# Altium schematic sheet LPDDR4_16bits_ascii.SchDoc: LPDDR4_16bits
size A3; Date: Not used; ApprovedBy: Not used; CheckedBy: Not used; Author: Not used; CompanyName: STMicroelectronics; DrawnBy: Not used; Engineer: Not used; Organization: Not used; Address1: Not used; Address2: Not used; Address3: Not used; Address4: Not used; DocumentNumber: 6; Revision: Not used; SheetNumber: 6; SheetTotal: 7
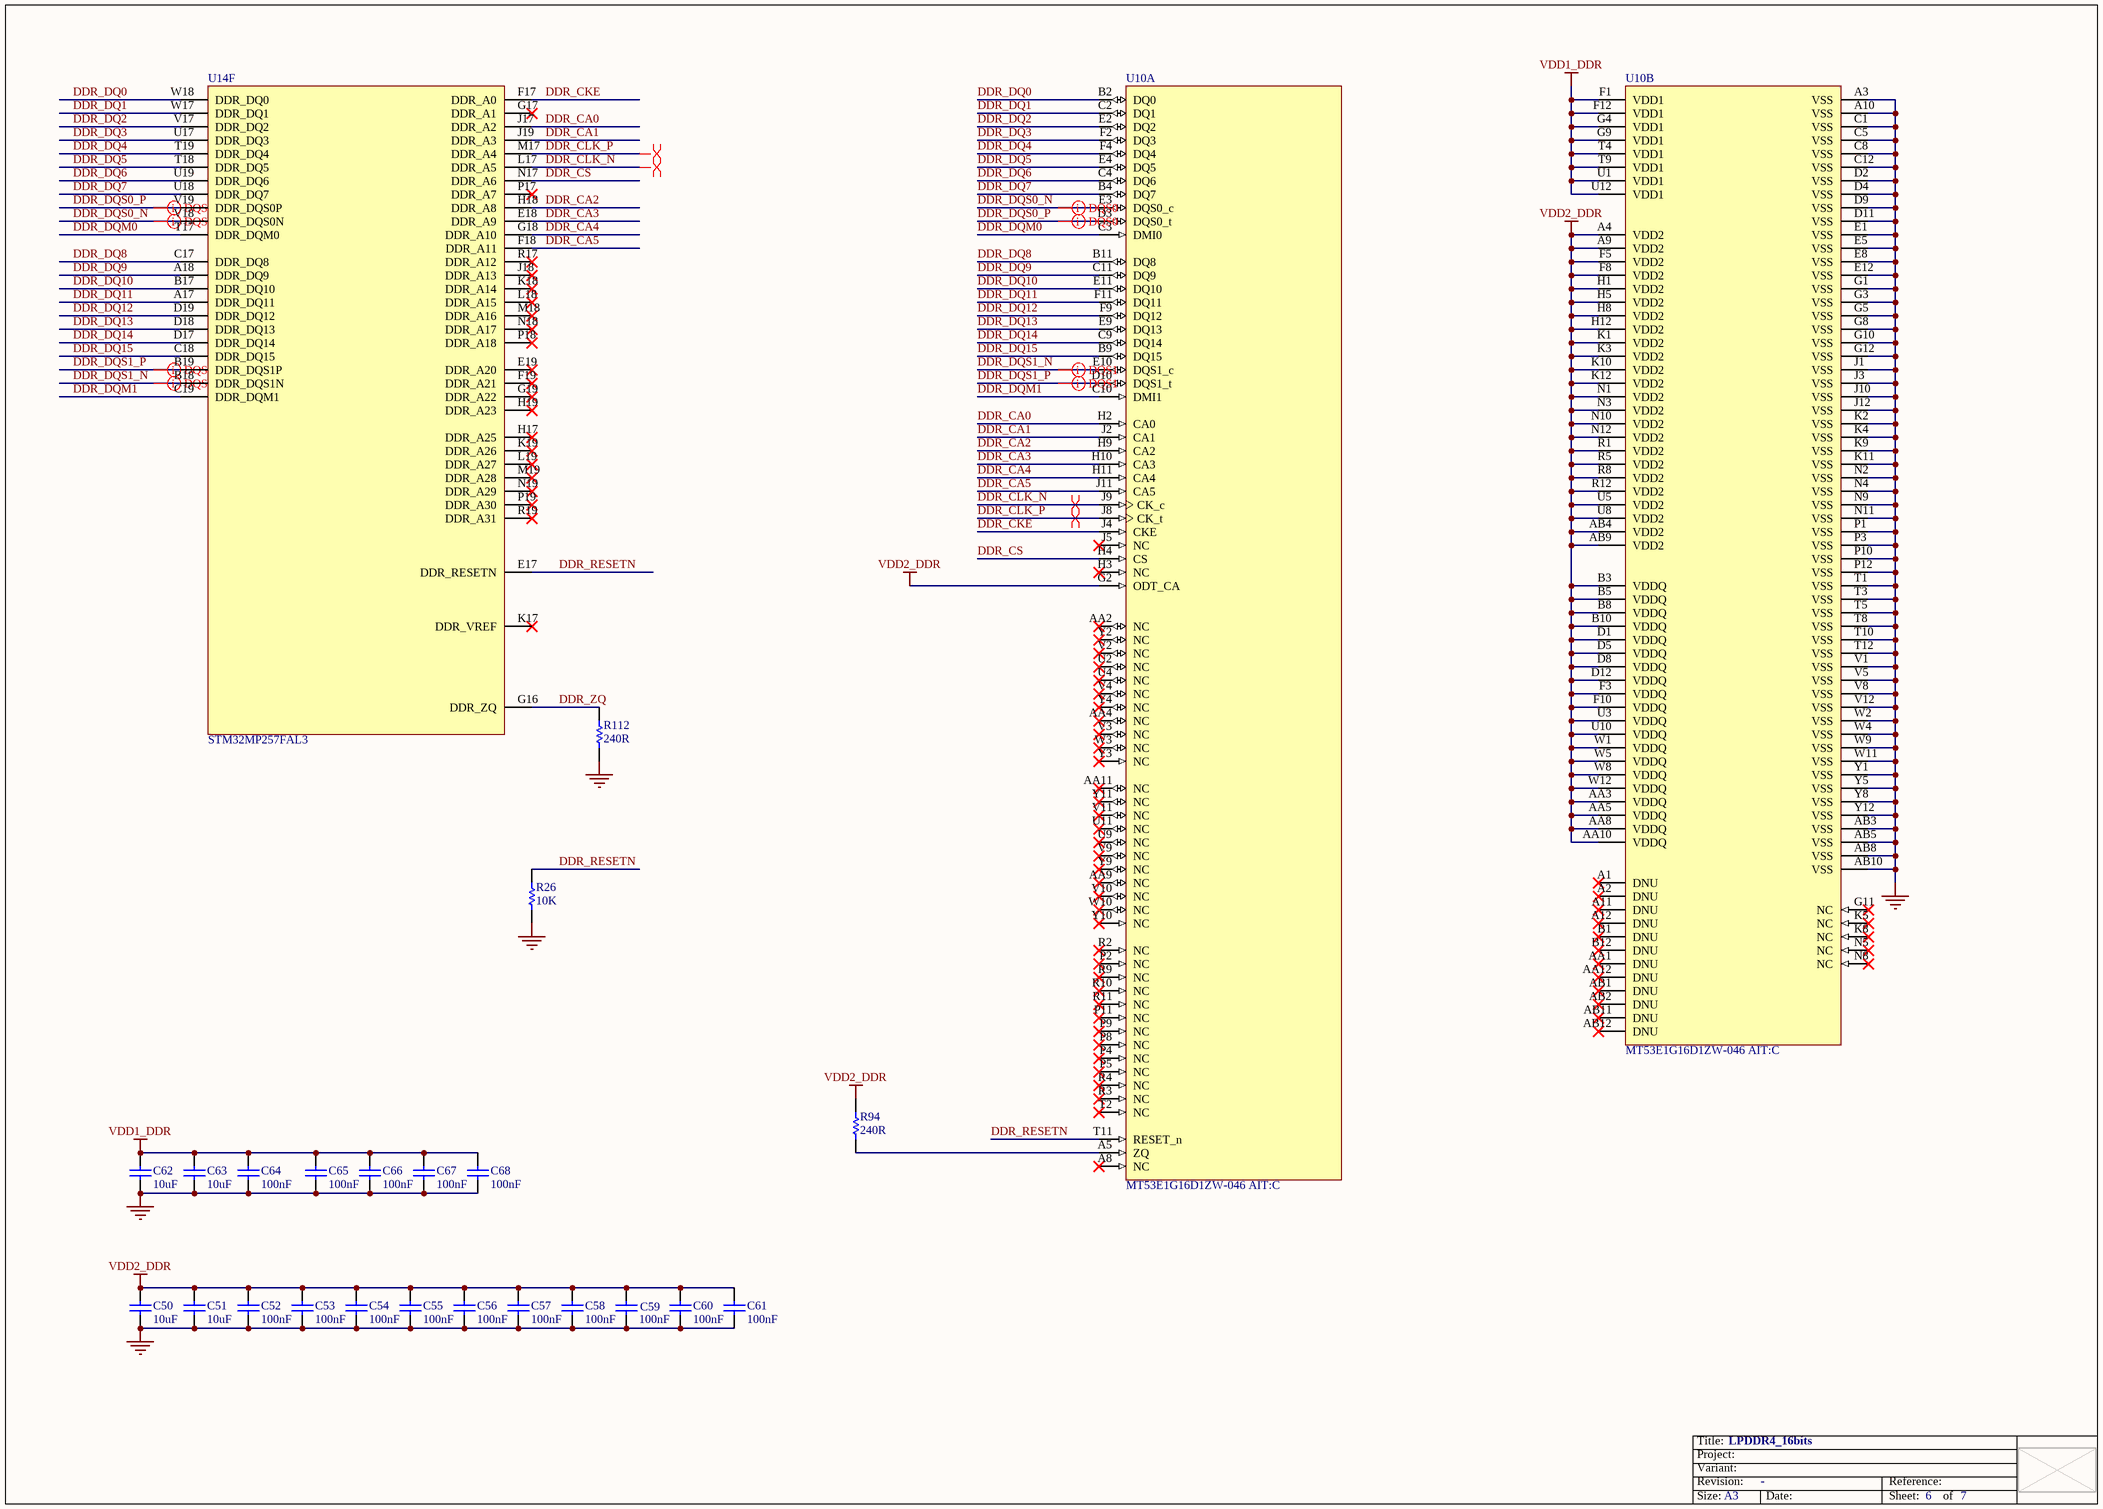
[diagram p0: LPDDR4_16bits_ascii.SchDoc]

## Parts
C50  value 10uF  [C0603]  (hidden comment: Capacitor)
C51  value 10uF  [C0603]  (hidden comment: Capacitor)
C52  value 100nF  [C0402]  (hidden comment: Capacitor)
C53  value 100nF  [C0402]  (hidden comment: Capacitor)
C54  value 100nF  [C0402]  (hidden comment: Capacitor)
C55  value 100nF  [C0402]  (hidden comment: Capacitor)
C56  value 100nF  [C0402]  (hidden comment: Capacitor)
C57  value 100nF  [C0402]  (hidden comment: Capacitor)
C58  value 100nF  [C0402]  (hidden comment: Capacitor)
C59  value 100nF  [C0402]  (hidden comment: Capacitor)
C60  value 100nF  [C0402]  (hidden comment: Capacitor)
C61  value 100nF  [C0402]  (hidden comment: Capacitor)
C62  value 10uF  [C0603]  (hidden comment: Capacitor)
C63  value 10uF  [C0603]  (hidden comment: Capacitor)
C64  value 100nF  [C0402]  (hidden comment: Capacitor)
C65  value 100nF  [C0402]  (hidden comment: Capacitor)
C66  value 100nF  [C0402]  (hidden comment: Capacitor)
C67  value 100nF  [C0402]  (hidden comment: Capacitor)
C68  value 100nF  [C0402]  (hidden comment: Capacitor)
R26  value 10K  [R0402]  (hidden comment: Resistor)
R94  value 240R  [R0201_H0P23]  (hidden comment: Resistor)
R112  value 240R  [R0201_H0P23]  (hidden comment: Resistor)
U10  MT53E1G16D1ZW-046 AIT:C  [ICC_TFBGA200_10X14P5_P080_H1P05]  (parts A,B of 2)
U14  STM32MP257FAL3  [ICC_VFBGA361_10X10_P050]  (part F of 8)

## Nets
GND: C50.1 C51.1 C52.1 C53.2 C54.2 C55.2 C56.2 C57.2 C58.2 C59.2 C60.2 C61.2 C62.1 C63.1 C64.1 C65.1 C66.1 C67.1 C68.1 R26.1 R112.1 U10.A3(VSS) U10.A10(VSS) U10.AB3(VSS) U10.AB5(VSS) U10.AB8(VSS) U10.AB10(VSS) U10.C1(VSS) U10.C5(VSS) U10.C8(VSS) U10.C12(VSS) U10.D2(VSS) U10.D4(VSS) U10.D9(VSS) U10.D11(VSS) U10.E1(VSS) U10.E5(VSS) U10.E8(VSS) U10.E12(VSS) U10.G1(VSS) U10.G3(VSS) U10.G5(VSS) U10.G8(VSS) U10.G10(VSS) U10.G12(VSS) U10.J1(VSS) U10.J3(VSS) U10.J10(VSS) U10.J12(VSS) U10.K2(VSS) U10.K4(VSS) U10.K9(VSS) U10.K11(VSS) U10.N2(VSS) U10.N4(VSS) U10.N9(VSS) U10.N11(VSS) U10.P1(VSS) U10.P3(VSS) U10.P10(VSS) U10.P12(VSS) U10.T1(VSS) U10.T3(VSS) U10.T5(VSS) U10.T8(VSS) U10.T10(VSS) U10.T12(VSS) U10.V1(VSS) U10.V5(VSS) U10.V8(VSS) U10.V12(VSS) U10.W2(VSS) U10.W4(VSS) U10.W9(VSS) U10.W11(VSS) U10.Y1(VSS) U10.Y5(VSS) U10.Y8(VSS) U10.Y12(VSS)
VDD1_DDR: C62.2 C63.2 C64.2 C65.2 C66.2 C67.2 C68.2 U10.F1(VDD1) U10.F12(VDD1) U10.G4(VDD1) U10.G9(VDD1) U10.T4(VDD1) U10.T9(VDD1) U10.U1(VDD1) U10.U12(VDD1)
VDD2_DDR: C50.2 C51.2 C52.2 C53.1 C54.1 C55.1 C56.1 C57.1 C58.1 C59.1 C60.1 C61.1 R94.2 U10.A4(VDD2) U10.A9(VDD2) U10.AA3(VDDQ) U10.AA5(VDDQ) U10.AA8(VDDQ) U10.AA10(VDDQ) U10.AB4(VDD2) U10.AB9(VDD2) U10.B3(VDDQ) U10.B5(VDDQ) U10.B8(VDDQ) U10.B10(VDDQ) U10.D1(VDDQ) U10.D5(VDDQ) U10.D8(VDDQ) U10.D12(VDDQ) U10.F3(VDDQ) U10.F5(VDD2) U10.F8(VDD2) U10.F10(VDDQ) U10.G2(ODT_CA) U10.H1(VDD2) U10.H5(VDD2) U10.H8(VDD2) U10.H12(VDD2) U10.K1(VDD2) U10.K3(VDD2) U10.K10(VDD2) U10.K12(VDD2) U10.N1(VDD2) U10.N3(VDD2) U10.N10(VDD2) U10.N12(VDD2) U10.R1(VDD2) U10.R5(VDD2) U10.R8(VDD2) U10.R12(VDD2) U10.U3(VDDQ) U10.U5(VDD2) U10.U8(VDD2) U10.U10(VDDQ) U10.W1(VDDQ) U10.W5(VDDQ) U10.W8(VDDQ) U10.W12(VDDQ)
DDR_CA0: U10.H2(CA0) U14.J17(DDR_A2)
DDR_CA1: U10.J2(CA1) U14.J19(DDR_A3)
DDR_CA2: U10.H9(CA2) U14.H18(DDR_A8)
DDR_CA3: U10.H10(CA3) U14.E18(DDR_A9)
DDR_CA4: U10.H11(CA4) U14.G18(DDR_A10)
DDR_CA5: U10.J11(CA5) U14.F18(DDR_A11)
DDR_CKE: U10.J4(CKE) U14.F17(DDR_A0)
DDR_CLK_N: U10.J9(CK_c) U14.L17(DDR_A5)
DDR_CLK_P: U10.J8(CK_t) U14.M17(DDR_A4)
DDR_CS: U10.H4(CS) U14.N17(DDR_A6)
DDR_DQ0: U10.B2(DQ0) U14.W18(DDR_DQ0)
DDR_DQ1: U10.C2(DQ1) U14.W17(DDR_DQ1)
DDR_DQ2: U10.E2(DQ2) U14.V17(DDR_DQ2)
DDR_DQ3: U10.F2(DQ3) U14.U17(DDR_DQ3)
DDR_DQ4: U10.F4(DQ4) U14.T19(DDR_DQ4)
DDR_DQ5: U10.E4(DQ5) U14.T18(DDR_DQ5)
DDR_DQ6: U10.C4(DQ6) U14.U19(DDR_DQ6)
DDR_DQ7: U10.B4(DQ7) U14.U18(DDR_DQ7)
DDR_DQ8: U10.B11(DQ8) U14.C17(DDR_DQ8)
DDR_DQ9: U10.C11(DQ9) U14.A18(DDR_DQ9)
DDR_DQ10: U10.E11(DQ10) U14.B17(DDR_DQ10)
DDR_DQ11: U10.F11(DQ11) U14.A17(DDR_DQ11)
DDR_DQ12: U10.F9(DQ12) U14.D19(DDR_DQ12)
DDR_DQ13: U10.E9(DQ13) U14.D18(DDR_DQ13)
DDR_DQ14: U10.C9(DQ14) U14.D17(DDR_DQ14)
DDR_DQ15: U10.B9(DQ15) U14.C18(DDR_DQ15)
DDR_DQM0: U10.C3(DMI0) U14.T17(DDR_DQM0)
DDR_DQM1: U10.C10(DMI1) U14.C19(DDR_DQM1)
DDR_DQS0_N: U10.E3(DQS0_c) U14.V18(DDR_DQS0N)
DDR_DQS0_P: U10.D3(DQS0_t) U14.V19(DDR_DQS0P)
DDR_DQS1_N: U10.E10(DQS1_c) U14.B18(DDR_DQS1N)
DDR_DQS1_P: U10.D10(DQS1_t) U14.B19(DDR_DQS1P)
DDR_RESETN: R26.2 U10.T11(RESET_n) U14.E17(DDR_RESETN)
DDR_ZQ: R112.2 U14.G16(DDR_ZQ)
NetR94_1: R94.1 U10.A5(ZQ)

Not connected (* = marked no-connect by the designer): U10 A1(DNU)* A2(DNU)* A8(NC)* A11(DNU)* A12(DNU)* AA1(DNU)* AA2(NC)* AA4(NC)* AA9(NC)* AA11(NC)* AA12(DNU)* AB1(DNU)* AB2(DNU)* AB11(DNU)* AB12(DNU)* B1(DNU)* B12(DNU)* G11(NC)* H3(NC)* J5(NC)* K5(NC)* K8(NC)* N5(NC)* N8(NC)* P2(NC)* P4(NC)* P5(NC)* P8(NC)* P9(NC)* P11(NC)* R2(NC)* R3(NC)* R4(NC)* R9(NC)* R10(NC)* R11(NC)* T2(NC)* U2(NC)* U4(NC)* U9(NC)* U11(NC)* V2(NC)* V3(NC)* V4(NC)* V9(NC)* V10(NC)* V11(NC)* W3(NC)* W10(NC)* Y2(NC)* Y3(NC)* Y4(NC)* Y9(NC)* Y10(NC)* Y11(NC)*; U14 E19(DDR_A20)* F19(DDR_A21)* G17(DDR_A1)* G19(DDR_A22)* H17(DDR_A25)* H19(DDR_A23)* J18(DDR_A13)* K17(DDR_VREF)* K18(DDR_A14)* K19(DDR_A26)* L18(DDR_A15)* L19(DDR_A27)* M18(DDR_A16)* M19(DDR_A28)* N18(DDR_A17)* N19(DDR_A29)* P17(DDR_A7)* P18(DDR_A18)* P19(DDR_A30)* R17(DDR_A12)* R19(DDR_A31)*

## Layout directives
differential pair: DDR_CLK_N, DDR_CLK_P, DDR_DQS0_N, DDR_DQS0_P, DDR_DQS1_N, DDR_DQS1_P

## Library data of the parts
C50 C51 C62 C63 = MCD-01341: Capacitor, MLCC, 10uF, 6V3, X5R, +/-20%, 0603, T=0.8mm; Part_Preference: Recommended; Manufacturer: MURATA; Manufacturer_Part_Number: GRM188R60J106ME47D; Component_Country_Of_Origin: Japan°°; ShowFields: YES; ID: 3441
C52-C61 C64-C68 = MCD-00006: Capacitor, MLCC, 100nF, 16V, X7R, +/-10%, 0402, T=0.5mm; Part_Preference: Recommended; Manufacturer: YAGEO; Manufacturer_Part_Number: CC0402KRX7R7BB104; Partial_Alternate_Internal_Part_Number: MCD-03299; Order_Code_RS: 9402047; Component_Country_Of_Origin: China; ShowFields: YES; ID: 2474
R26 = MCD-00053: Resistor, 10K, 0402, +/-1%, 1/16W; BMS_Part_Number: 9131590; Part_Preference: Recommended; Manufacturer: YAGEO; Manufacturer_Part_Number: RC0402FR-0710KL; Order_Code_RS: 9239359; Component_Country_Of_Origin: China; ShowFields: YES; ID: 2539
R94 R112 = MCD-02253: Resistor, 240R, 0201, +/-1%, 1/20W; Part_Preference: Recommended; Manufacturer: YAGEO; Manufacturer_Part_Number: RC0201FR-07240RL; Component_Country_Of_Origin: China; ShowFields: YES; ID: 4353
U10 = MCD-04012: Memory, SDRAM, 1V1, 16Gbit, 4266MHz; Part_Type: IC; Part_Preference: Recommended; Manufacturer: MICRON; Component_Country_Of_Origin: Taiwan°; ShowFields: YES; ID: 6128
U14 = MCD-03768: MPU, dual core ARM cortex-A35 64-bit + M33 32-bit, 808KB SRAM, With Crypto; Part_Type: IC; Part_Preference: Recommended; Manufacturer: STMICROELECTRONICS; Component_Country_Of_Origin: Unknown; ShowFields: YES; ID: 5884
